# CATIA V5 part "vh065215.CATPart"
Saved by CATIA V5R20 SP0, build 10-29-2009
Part number: VH06_1
Revision: ANY
Definition: UNKNOWN
Nomenclature: VH06_1
Source: Unknown
Bounding box of the stored display mesh (mm): x -3 to 2.986, y -2.9 to 12.1, z -3 to 3
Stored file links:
  C:\Users\Utente\Desktop\IO LAVORO\3D X SITO CF\CUMSA\3D files VH\vh065215.CATPart
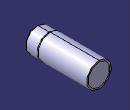
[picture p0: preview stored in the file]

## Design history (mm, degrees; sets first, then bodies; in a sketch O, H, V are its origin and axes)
Body1 "VA-06_variante_antigiro_2-1-solid1" (main body)
  Solid1: solid without history
Body2 "VA-06_Tuerca_giro_v2_acabado_2-1-solid1"
  Solid2: solid without history
Body3 "VA-06 Obturador_aire_2-1-solid1"
  Solid3: solid without history
Body4 "VA-06 tapa_acabado_2-1-solid1"
  Solid4: solid without history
